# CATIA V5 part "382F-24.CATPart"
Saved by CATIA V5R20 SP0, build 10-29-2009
Part number: 382F-24
Definition: NONE
Nomenclature: 382F-24
Source: Unknown
Description: 382F-24
Bounding box of the stored display mesh (mm): x -6 to 15, y -12 to 12, z -11.818 to 11.818
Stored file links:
  C:\Users\Utente\Desktop\IO LAVORO\3D X SITO CF\X SITO\PLASTICA\382F\382F-24.CATPart
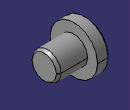
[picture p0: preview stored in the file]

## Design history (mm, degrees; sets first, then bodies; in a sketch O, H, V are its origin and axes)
Body1 "382F-24" (main body)
  Solid1: solid without history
